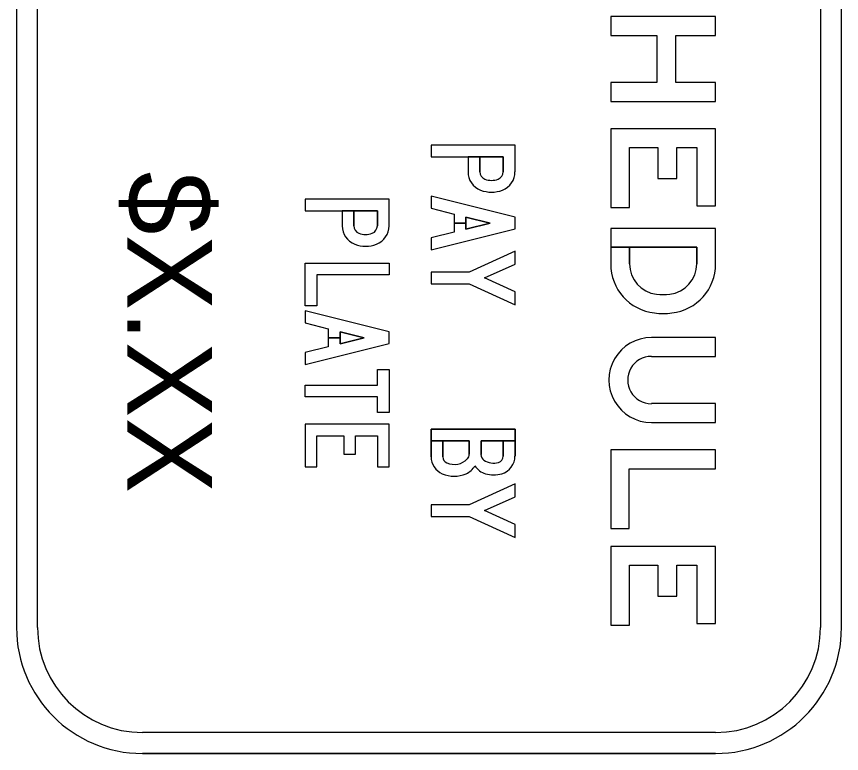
# Model space of a CAD drawing. Extents: x 46672 to 47298, y 5424 to 5742.
# Drawn here: x 47135.78 to 47160.56, y 5553.74 to 5575.87 of the extents above; entities that cross this region are included whole.
import ezdxf

# ---------------------------------------------------------------- set-up
doc = ezdxf.new("R2010")
doc.units = 0
doc.layers.add('TextNotes', color=7, linetype='Continuous')

msp = doc.modelspace()

# ---------------------------------------------------------------- linework, layer by layer
at = {"layer": 'TextNotes'}
for p, q in [((47135.782, 5598.474), (47135.782, 5557.522)), ((47136.412, 5557.522), (47136.412, 5598.474)), ((47159.925, 5598.474), (47159.925, 5557.522)), ((47160.555, 5557.522), (47160.555, 5598.474)), ((47150.752, 5571.211), (47150.752, 5572.009)), ((47146.971, 5569.587), (47146.971, 5570.385)), ((47153.624, 5568.941), (47153.624, 5568.442)), ((47153.624, 5568.941), (47153.624, 5568.442)), ((47154.191, 5568.941), (47154.191, 5568.442)), ((47156.775, 5564.247), (47154.845, 5564.247)), ((47156.775, 5564.247), (47154.845, 5564.247)), ((47156.775, 5564.247), (47154.845, 5564.247)), ((47156.775, 5554.371), (47139.563, 5554.371)), ((47156.775, 5553.741), (47139.563, 5553.741)), ((47139.563, 5553.741), (47156.775, 5553.741))]:
    msp.add_line(p, q, dxfattribs=at)
for points in [[(47155.578, 5573.887), (47155.578, 5575.304), (47156.775, 5575.304), (47156.775, 5575.871), (47153.624, 5575.871), (47153.624, 5575.304), (47155.011, 5575.304), (47155.011, 5573.887), (47153.624, 5573.887), (47153.624, 5573.32), (47156.775, 5573.32), (47156.775, 5573.887)], [(47155.578, 5573.887), (47155.578, 5575.304), (47156.775, 5575.304), (47156.775, 5575.871), (47153.624, 5575.871), (47153.624, 5575.304), (47155.011, 5575.304), (47155.011, 5573.887), (47153.624, 5573.887), (47153.624, 5573.32), (47156.775, 5573.32), (47156.775, 5573.887)], [(47155.578, 5573.887), (47155.578, 5575.304), (47156.775, 5575.304), (47156.775, 5575.871), (47153.624, 5575.871), (47153.624, 5575.304), (47155.011, 5575.304), (47155.011, 5573.887), (47153.624, 5573.887), (47153.624, 5573.32), (47156.775, 5573.32), (47156.775, 5573.887)], [(47154.191, 5570.138), (47154.191, 5571.934), (47155.039, 5571.934), (47155.039, 5571.004), (47155.606, 5571.004), (47155.606, 5571.934), (47156.208, 5571.934), (47156.208, 5570.185), (47156.775, 5570.185), (47156.775, 5572.501), (47153.624, 5572.501), (47153.624, 5570.138)], [(47154.191, 5570.138), (47154.191, 5571.934), (47155.039, 5571.934), (47155.039, 5571.004), (47155.606, 5571.004), (47155.606, 5571.934), (47156.208, 5571.934), (47156.208, 5570.185), (47156.775, 5570.185), (47156.775, 5572.501), (47153.624, 5572.501), (47153.624, 5570.138)], [(47154.191, 5570.138), (47154.191, 5571.934), (47155.039, 5571.934), (47155.039, 5571.004), (47155.606, 5571.004), (47155.606, 5571.934), (47156.208, 5571.934), (47156.208, 5570.185), (47156.775, 5570.185), (47156.775, 5572.501), (47153.624, 5572.501), (47153.624, 5570.138)], [(47148.924, 5569.939), (47148.924, 5569.399), (47148.231, 5569.226), (47148.231, 5568.863), (47150.752, 5569.493), (47150.752, 5569.845), (47148.231, 5570.476), (47148.231, 5570.112)], [(47149.277, 5569.669), (47149.277, 5569.85), (47150.002, 5569.669), (47149.277, 5569.488), (47149.277, 5569.669), (47148.924, 5569.669), (47148.924, 5569.399), (47148.231, 5569.226), (47148.231, 5568.863), (47150.752, 5569.493), (47150.752, 5569.845), (47148.231, 5570.476), (47148.231, 5570.112), (47148.924, 5569.939), (47148.924, 5569.669)], [(47149.277, 5569.669), (47149.277, 5569.85), (47150.002, 5569.669), (47149.277, 5569.488), (47149.277, 5569.669), (47148.924, 5569.669), (47148.924, 5569.399), (47148.231, 5569.226), (47148.231, 5568.863), (47150.752, 5569.493), (47150.752, 5569.845), (47148.231, 5570.476), (47148.231, 5570.112), (47148.924, 5569.939), (47148.924, 5569.669)], [(47149.277, 5569.488), (47150.002, 5569.669), (47149.277, 5569.85)], [(47149.378, 5568.198), (47148.231, 5568.198), (47148.231, 5567.845), (47149.378, 5567.845), (47150.752, 5567.215), (47150.752, 5567.603), (47149.84, 5568.021), (47150.752, 5568.439), (47150.752, 5568.828)], [(47149.378, 5568.198), (47148.231, 5568.198), (47148.231, 5567.845), (47149.378, 5567.845), (47150.752, 5567.215), (47150.752, 5567.603), (47149.84, 5568.021), (47150.752, 5568.439), (47150.752, 5568.828)], [(47149.378, 5568.198), (47148.231, 5568.198), (47148.231, 5567.845), (47149.378, 5567.845), (47150.752, 5567.215), (47150.752, 5567.603), (47149.84, 5568.021), (47150.752, 5568.439), (47150.752, 5568.828)], [(47146.971, 5568.47), (47146.971, 5568.117), (47144.804, 5568.117), (47144.804, 5567.185), (47144.451, 5567.185), (47144.451, 5568.47)], [(47146.971, 5568.47), (47146.971, 5568.117), (47144.804, 5568.117), (47144.804, 5567.185), (47144.451, 5567.185), (47144.451, 5568.47)], [(47146.971, 5568.47), (47146.971, 5568.117), (47144.804, 5568.117), (47144.804, 5567.185), (47144.451, 5567.185), (47144.451, 5568.47)], [(47145.144, 5566.496), (47145.144, 5565.957), (47144.451, 5565.784), (47144.451, 5565.42), (47146.971, 5566.05), (47146.971, 5566.403), (47144.451, 5567.033), (47144.451, 5566.67)], [(47145.497, 5566.227), (47145.497, 5566.408), (47146.222, 5566.227), (47145.497, 5566.046), (47145.497, 5566.227), (47145.144, 5566.227), (47145.144, 5565.957), (47144.451, 5565.784), (47144.451, 5565.42), (47146.971, 5566.05), (47146.971, 5566.403), (47144.451, 5567.033), (47144.451, 5566.67), (47145.144, 5566.496), (47145.144, 5566.227)], [(47145.497, 5566.227), (47145.497, 5566.408), (47146.222, 5566.227), (47145.497, 5566.046), (47145.497, 5566.227), (47145.144, 5566.227), (47145.144, 5565.957), (47144.451, 5565.784), (47144.451, 5565.42), (47146.971, 5566.05), (47146.971, 5566.403), (47144.451, 5567.033), (47144.451, 5566.67), (47145.144, 5566.496), (47145.144, 5566.227)], [(47145.497, 5566.046), (47146.222, 5566.227), (47145.497, 5566.408)], [(47146.618, 5564.803), (47146.618, 5565.269), (47146.971, 5565.269), (47146.971, 5563.984), (47146.618, 5563.984), (47146.618, 5564.45), (47144.451, 5564.45), (47144.451, 5564.803)], [(47146.618, 5564.803), (47146.618, 5565.269), (47146.971, 5565.269), (47146.971, 5563.984), (47146.618, 5563.984), (47146.618, 5564.45), (47144.451, 5564.45), (47144.451, 5564.803)], [(47146.618, 5564.803), (47146.618, 5565.269), (47146.971, 5565.269), (47146.971, 5563.984), (47146.618, 5563.984), (47146.618, 5564.45), (47144.451, 5564.45), (47144.451, 5564.803)], [(47144.804, 5563.278), (47145.61, 5563.278), (47145.61, 5562.726), (47145.963, 5562.726), (47145.963, 5563.278), (47146.618, 5563.278), (47146.618, 5562.346), (47146.971, 5562.346), (47146.971, 5563.631), (47144.451, 5563.631), (47144.451, 5562.346), (47144.804, 5562.346)], [(47144.804, 5563.278), (47145.61, 5563.278), (47145.61, 5562.726), (47145.963, 5562.726), (47145.963, 5563.278), (47146.618, 5563.278), (47146.618, 5562.346), (47146.971, 5562.346), (47146.971, 5563.631), (47144.451, 5563.631), (47144.451, 5562.346), (47144.804, 5562.346)], [(47144.804, 5563.278), (47145.61, 5563.278), (47145.61, 5562.726), (47145.963, 5562.726), (47145.963, 5563.278), (47146.618, 5563.278), (47146.618, 5562.346), (47146.971, 5562.346), (47146.971, 5563.631), (47144.451, 5563.631), (47144.451, 5562.346), (47144.804, 5562.346)], [(47153.624, 5560.498), (47154.176, 5560.498), (47154.176, 5562.293), (47156.775, 5562.293), (47156.775, 5562.86), (47153.624, 5562.86)], [(47153.624, 5560.498), (47154.176, 5560.498), (47154.176, 5562.293), (47156.775, 5562.293), (47156.775, 5562.86), (47153.624, 5562.86)], [(47153.624, 5560.498), (47154.176, 5560.498), (47154.176, 5562.293), (47156.775, 5562.293), (47156.775, 5562.86), (47153.624, 5562.86)], [(47149.378, 5561.212), (47148.231, 5561.212), (47148.231, 5560.859), (47149.378, 5560.859), (47150.752, 5560.229), (47150.752, 5560.617), (47149.84, 5561.035), (47150.752, 5561.453), (47150.752, 5561.842)], [(47149.378, 5561.212), (47148.231, 5561.212), (47148.231, 5560.859), (47149.378, 5560.859), (47150.752, 5560.229), (47150.752, 5560.617), (47149.84, 5561.035), (47150.752, 5561.453), (47150.752, 5561.842)], [(47149.378, 5561.212), (47148.231, 5561.212), (47148.231, 5560.859), (47149.378, 5560.859), (47150.752, 5560.229), (47150.752, 5560.617), (47149.84, 5561.035), (47150.752, 5561.453), (47150.752, 5561.842)], [(47154.191, 5557.599), (47154.191, 5559.395), (47155.039, 5559.395), (47155.039, 5558.466), (47155.606, 5558.466), (47155.606, 5559.395), (47156.208, 5559.395), (47156.208, 5557.647), (47156.775, 5557.647), (47156.775, 5559.962), (47153.624, 5559.962), (47153.624, 5557.599)], [(47154.191, 5557.599), (47154.191, 5559.395), (47155.039, 5559.395), (47155.039, 5558.466), (47155.606, 5558.466), (47155.606, 5559.395), (47156.208, 5559.395), (47156.208, 5557.647), (47156.775, 5557.647), (47156.775, 5559.962), (47153.624, 5559.962), (47153.624, 5557.599)], [(47154.191, 5557.599), (47154.191, 5559.395), (47155.039, 5559.395), (47155.039, 5558.466), (47155.606, 5558.466), (47155.606, 5559.395), (47156.208, 5559.395), (47156.208, 5557.647), (47156.775, 5557.647), (47156.775, 5559.962), (47153.624, 5559.962), (47153.624, 5557.599)]]:
    msp.add_lwpolyline(points, close=True, dxfattribs=at)
for points in [[(47150.752, 5572.009), (47148.231, 5572.009), (47148.231, 5571.657), (47149.34, 5571.657), (47149.34, 5571.211)], [(47150.752, 5571.211), (47150.752, 5572.009), (47148.231, 5572.009), (47148.231, 5571.657), (47150.399, 5571.657), (47150.399, 5571.211)], [(47150.752, 5571.211), (47150.752, 5572.009), (47148.231, 5572.009), (47148.231, 5571.657), (47150.399, 5571.657), (47150.399, 5571.211)], [(47149.693, 5571.211), (47149.693, 5571.656), (47149.34, 5571.656), (47149.34, 5571.211)], [(47149.693, 5571.211), (47149.693, 5571.656), (47149.34, 5571.656), (47149.34, 5571.211)], [(47150.399, 5571.211), (47150.399, 5571.657), (47149.693, 5571.657), (47149.693, 5571.211)], [(47146.971, 5570.385), (47144.451, 5570.385), (47144.451, 5570.033), (47145.56, 5570.033), (47145.56, 5569.587)], [(47146.971, 5569.587), (47146.971, 5570.385), (47144.451, 5570.385), (47144.451, 5570.033), (47146.618, 5570.033), (47146.618, 5569.587)], [(47146.971, 5569.587), (47146.971, 5570.385), (47144.451, 5570.385), (47144.451, 5570.033), (47146.618, 5570.033), (47146.618, 5569.587)], [(47145.913, 5569.587), (47145.913, 5570.032), (47145.56, 5570.032), (47145.56, 5569.587)], [(47145.913, 5569.587), (47145.913, 5570.032), (47145.56, 5570.032), (47145.56, 5569.587)], [(47146.618, 5569.587), (47146.618, 5570.033), (47145.913, 5570.033), (47145.913, 5569.587)], [(47156.775, 5568.442), (47156.775, 5569.508), (47153.624, 5569.508), (47153.624, 5568.442)], [(47156.775, 5568.442), (47156.775, 5569.508), (47153.624, 5569.508), (47153.624, 5568.941), (47156.208, 5568.941), (47156.208, 5568.442)], [(47156.775, 5568.442), (47156.775, 5569.508), (47153.624, 5569.508), (47153.624, 5568.941), (47156.208, 5568.941), (47156.208, 5568.442)], [(47154.191, 5568.442), (47154.191, 5568.941), (47153.624, 5568.941)], [(47154.191, 5568.442), (47154.191, 5568.941), (47153.624, 5568.941)], [(47156.208, 5568.442), (47156.208, 5568.941), (47154.191, 5568.941)], [(47154.845, 5565.664), (47156.775, 5565.664), (47156.775, 5566.231), (47154.845, 5566.231)], [(47154.845, 5565.664), (47156.775, 5565.664), (47156.775, 5566.231), (47154.845, 5566.231)], [(47154.845, 5565.664), (47156.775, 5565.664), (47156.775, 5566.231), (47154.845, 5566.231)], [(47154.845, 5563.68), (47156.775, 5563.68), (47156.775, 5564.247)], [(47154.845, 5563.68), (47156.775, 5563.68), (47156.775, 5564.247)], [(47154.845, 5563.68), (47156.775, 5563.68), (47156.775, 5564.247)], [(47150.752, 5562.673), (47150.752, 5563.48), (47148.231, 5563.48), (47148.231, 5562.651)], [(47149.378, 5562.729), (47149.378, 5563.127), (47148.231, 5563.127), (47148.231, 5563.48), (47150.752, 5563.48), (47150.752, 5563.127), (47149.731, 5563.127), (47149.731, 5562.715)], [(47149.378, 5562.729), (47149.378, 5563.127), (47148.231, 5563.127), (47148.231, 5563.48), (47150.752, 5563.48), (47150.752, 5563.127), (47149.731, 5563.127), (47149.731, 5562.715)], [(47148.231, 5562.651), (47148.231, 5563.127), (47148.584, 5563.127), (47148.584, 5562.651)], [(47148.231, 5562.651), (47148.231, 5563.127), (47148.584, 5563.127), (47148.584, 5562.651)], [(47148.584, 5562.651), (47148.584, 5563.127), (47149.378, 5563.127), (47149.378, 5562.729)], [(47149.731, 5562.715), (47149.731, 5563.127), (47150.399, 5563.127), (47150.399, 5562.673)], [(47150.399, 5562.673), (47150.399, 5563.127), (47150.752, 5563.127), (47150.752, 5562.673)], [(47150.399, 5562.673), (47150.399, 5563.127), (47150.752, 5563.127), (47150.752, 5562.673)]]:
    msp.add_lwpolyline(points, dxfattribs=at)
for centre, radius, start, end in [((47148.786, 5562.651), 0.554, 180, 246.8676), ((47148.786, 5562.651), 0.554, 180, 246.8676), ((47148.786, 5562.651), 0.554, 180, 246.8676), ((47148.786, 5562.651), 0.202, 180, 246.8676), ((47148.786, 5562.651), 0.202, 180, 246.8676), ((47148.786, 5562.651), 0.202, 180, 246.8676), ((47148.924, 5562.976), 0.554, 246.8676, 315.5847), ((47148.924, 5562.976), 0.554, 246.8676, 315.5847), ((47148.924, 5562.976), 0.554, 246.8676, 315.5847), ((47149.176, 5562.729), 0.202, 315.5847, 0), ((47149.176, 5562.729), 0.202, 315.5847, 0), ((47149.176, 5562.729), 0.202, 315.5847, 0), ((47149.932, 5562.715), 0.202, 180, 235.9442), ((47149.932, 5562.715), 0.202, 180, 235.9442), ((47149.932, 5562.715), 0.202, 180, 235.9442), ((47150.109, 5562.976), 0.517, 235.9442, 286.2602), ((47150.109, 5562.976), 0.517, 235.9442, 286.2602), ((47150.109, 5562.976), 0.517, 235.9442, 286.2602), ((47150.197, 5562.673), 0.202, 286.2602, 0), ((47150.197, 5562.673), 0.202, 286.2602, 0), ((47150.197, 5562.673), 0.202, 286.2602, 0), ((47150.197, 5562.673), 0.554, 286.2602, 0), ((47150.197, 5562.673), 0.554, 286.2602, 0), ((47150.197, 5562.673), 0.554, 286.2602, 0), ((47149.063, 5562.651), 0.554, 293.1324, 331.0715), ((47149.063, 5562.651), 0.554, 293.1324, 331.0715), ((47149.063, 5562.651), 0.554, 293.1324, 331.0715), ((47150.021, 5562.673), 0.554, 211.5648, 253.7398), ((47150.021, 5562.673), 0.554, 211.5648, 253.7398), ((47150.021, 5562.673), 0.554, 211.5648, 253.7398), ((47148.924, 5562.976), 0.907, 246.8676, 293.1324), ((47148.924, 5562.976), 0.907, 246.8676, 293.1324), ((47148.924, 5562.976), 0.907, 246.8676, 293.1324), ((47150.109, 5562.976), 0.87, 253.7398, 286.2602), ((47150.109, 5562.976), 0.87, 253.7398, 286.2602), ((47150.109, 5562.976), 0.87, 253.7398, 286.2602), ((47139.563, 5557.522), 3.78, 180, 270), ((47139.563, 5557.522), 3.78, 180, 270), ((47139.563, 5557.522), 3.15, 180, 270), ((47156.775, 5557.522), 3.78, 270, 0), ((47156.775, 5557.522), 3.78, 270, 0), ((47156.775, 5557.522), 3.15, 270, 0)]:
    msp.add_arc(centre, radius, start, end, dxfattribs=at)
for centre, major_axis, ratio, start_param, end_param in [((47149.932, 5571.211), (0.592, 0), 0.999996, 3.141593, 4.344121), ((47149.932, 5571.211), (0.592, 0), 0.999996, 3.141593, 4.344121), ((47149.932, 5571.211), (0.592, 0), 0.999996, 3.141593, 4.344121), ((47149.932, 5571.211), (0.239, 0), 0.999996, 3.141593, 4.344121), ((47149.932, 5571.211), (0.239, 0), 0.999996, 3.141593, 4.344121), ((47149.932, 5571.211), (0.239, 0), 0.999996, 3.141593, 4.344121), ((47150.159, 5571.211), (0.239, 0), 0.999996, 5.080657, 6.283185), ((47150.159, 5571.211), (0.239, 0), 0.999996, 5.080657, 6.283185), ((47150.159, 5571.211), (0.239, 0), 0.999996, 5.080657, 6.283185), ((47150.159, 5571.211), (0.592, 0), 0.999996, 5.080657, 6.283185), ((47150.159, 5571.211), (0.592, 0), 0.999996, 5.080657, 6.283185), ((47150.159, 5571.211), (0.592, 0), 0.999996, 5.080657, 6.283185), ((47150.046, 5571.505), (0.554, 0), 0.999996, 4.344121, 5.080657), ((47150.046, 5571.505), (0.554, 0), 0.999996, 4.344121, 5.080657), ((47150.046, 5571.505), (0.554, 0), 0.999996, 4.344121, 5.080657), ((47150.046, 5571.505), (0.907, 0), 0.999996, 4.344121, 5.080657), ((47150.046, 5571.505), (0.907, 0), 0.999996, 4.344121, 5.080657), ((47150.046, 5571.505), (0.907, 0), 0.999996, 4.344121, 5.080657), ((47146.152, 5569.587), (0.592, 0), 0.999996, 3.141593, 4.344121), ((47146.152, 5569.587), (0.592, 0), 0.999996, 3.141593, 4.344121), ((47146.152, 5569.587), (0.592, 0), 0.999996, 3.141593, 4.344121), ((47146.152, 5569.587), (0.239, 0), 0.999996, 3.141593, 4.344121), ((47146.152, 5569.587), (0.239, 0), 0.999996, 3.141593, 4.344121), ((47146.152, 5569.587), (0.239, 0), 0.999996, 3.141593, 4.344121), ((47146.379, 5569.587), (0.239, 0), 0.999996, 5.080657, 6.283185), ((47146.379, 5569.587), (0.239, 0), 0.999996, 5.080657, 6.283185), ((47146.379, 5569.587), (0.239, 0), 0.999996, 5.080657, 6.283185), ((47146.379, 5569.587), (0.592, 0), 0.999996, 5.080657, 6.283185), ((47146.379, 5569.587), (0.592, 0), 0.999996, 5.080657, 6.283185), ((47146.379, 5569.587), (0.592, 0), 0.999996, 5.080657, 6.283185), ((47146.265, 5569.881), (0.554, 0), 0.999996, 4.344121, 5.080657), ((47146.265, 5569.881), (0.554, 0), 0.999996, 4.344121, 5.080657), ((47146.265, 5569.881), (0.554, 0), 0.999996, 4.344121, 5.080657), ((47146.265, 5569.881), (0.907, 0), 0.999996, 4.344121, 5.080657), ((47146.265, 5569.881), (0.907, 0), 0.999996, 4.344121, 5.080657), ((47146.265, 5569.881), (0.907, 0), 0.999996, 4.344121, 5.080657), ((47155.105, 5568.442), (1.481, 0), 0.999995, 3.141593, 4.598938), ((47155.105, 5568.442), (1.481, 0), 0.999995, 3.141593, 4.598938), ((47155.105, 5568.442), (1.481, 0), 0.999995, 3.141593, 4.598938), ((47155.105, 5568.442), (0.914, 0), 0.999995, 3.141593, 4.598938), ((47155.105, 5568.442), (0.914, 0), 0.999995, 3.141593, 4.598938), ((47155.105, 5568.442), (0.914, 0), 0.999995, 3.141593, 4.598938), ((47155.294, 5568.442), (0.914, 0), 0.999995, 4.82584, 6.283185), ((47155.294, 5568.442), (0.914, 0), 0.999995, 4.82584, 6.283185), ((47155.294, 5568.442), (0.914, 0), 0.999995, 4.82584, 6.283185), ((47155.294, 5568.442), (1.481, 0), 0.999995, 4.82584, 6.283185), ((47155.294, 5568.442), (1.481, 0), 0.999995, 4.82584, 6.283185), ((47155.294, 5568.442), (1.481, 0), 0.999995, 4.82584, 6.283185), ((47155.2, 5569.271), (1.748, 0), 0.999995, 4.598938, 4.82584), ((47155.2, 5569.271), (1.748, 0), 0.999995, 4.598938, 4.82584), ((47155.2, 5569.271), (1.748, 0), 0.999995, 4.598938, 4.82584), ((47155.2, 5569.271), (2.316, 0), 0.999995, 4.598938, 4.82584), ((47155.2, 5569.271), (2.316, 0), 0.999995, 4.598938, 4.82584), ((47155.2, 5569.271), (2.316, 0), 0.999995, 4.598938, 4.82584), ((47154.845, 5564.955), (1.276, 0), 0.999995, 1.570796, 4.712389), ((47154.845, 5564.955), (1.276, 0), 0.999995, 1.570796, 4.712389), ((47154.845, 5564.955), (1.276, 0), 0.999995, 1.570796, 4.712389), ((47154.845, 5564.955), (0.709, 0), 0.999995, 1.570796, 4.712389), ((47154.845, 5564.955), (0.709, 0), 0.999995, 1.570796, 4.712389), ((47154.845, 5564.955), (0.709, 0), 0.999995, 1.570796, 4.712389)]:
    msp.add_ellipse(centre, major_axis=major_axis, ratio=ratio, start_param=start_param, end_param=end_param, dxfattribs=at)

# ---------------------------------------------------------------- texts
msp.add_text('$X.XX', height=2.5485, rotation=270, dxfattribs=at).set_placement((47139.106, 5571.219))

doc.saveas('drawing.dxf')
